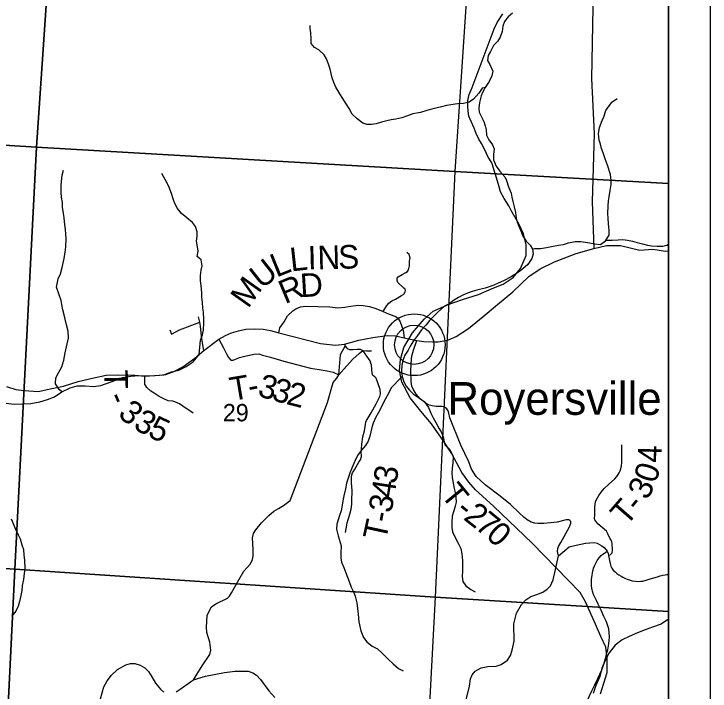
# Model space of a CAD drawing. Extents: x 0 to 44, y -23.8 to 22.
# Drawn here: x 7.321 to 9, y 15.074 to 16.706 of the extents above; entities that cross this region are included whole.
import ezdxf

# ---------------------------------------------------------------- set-up
doc = ezdxf.new("R2010")
doc.units = 0
for name, color, linetype in [('Default', 7, 'Continuous'), ('GM_X_County_Road', 7, 'Continuous'), ('GM_X_Minor_River', 7, 'Continuous'), ('GM_X_Rail_Line', 7, 'Continuous'), ('GM_X_Section', 7, 'Continuous'), ('GM_X_Section_Text', 7, 'Continuous'), ('GM_X_Township_Road', 7, 'Continuous'), ('GM_X_Township_Road_Text', 7, 'Continuous'), ('GM_X_Unincorporated', 7, 'Continuous'), ('GM_X_Unincorporated_Location', 7, 'Continuous'), ('GM_X_Unincorporated_Text', 7, 'Continuous'), ('SH_Cut_Line', 7, 'Continuous'), ('SH_Data', 7, 'Continuous')]:
    doc.layers.add(name, color=color, linetype=linetype)

msp = doc.modelspace()

# ---------------------------------------------------------------- linework, layer by layer
at = {"layer": 'Default'}
msp.add_lwpolyline([(7.2787, 14.3616), (7.5613, 14.343), (8.045, 14.3111), (8.4778, 14.2825), (8.9, 14.2547), (8.9, 20.3521), (8.6785, 20.3684), (7.6577, 20.4476), (7.4495, 20.4611), (7.016, 20.4891)], dxfattribs=at)
for points in [[(8.9, 16.2979), (8.9, 17.3085), (8.4522, 17.3376), (8.3848, 16.3266)], [(8.9, 15.2663), (8.9, 16.2979), (8.3848, 16.3266), (8.3369, 15.3004)], [(8.9, 14.2455), (8.9, 15.2663), (8.3369, 15.3004), (8.2829, 14.2852)]]:
    msp.add_lwpolyline(points, close=True, dxfattribs=at)
at = {"layer": 'GM_X_County_Road'}
for points in [[(7.3035, 15.808), (7.3263, 15.8012), (7.3453, 15.7989), (7.381, 15.7962), (7.4091, 15.8025), (7.4406, 15.8091), (7.4761, 15.8202), (7.5144, 15.8296), (7.5439, 15.8357), (7.5709, 15.8361), (7.6133, 15.8353), (7.6373, 15.8336), (7.6712, 15.8354), (7.688, 15.8377), (7.7072, 15.8445), (7.729, 15.8555), (7.7579, 15.8767), (7.7796, 15.8948), (7.8153, 15.9221), (7.8316, 15.9312), (7.846, 15.9381), (7.8626, 15.9427), (7.8809, 15.9463), (7.9005, 15.9476), (7.9224, 15.9469), (7.9397, 15.9437), (7.9599, 15.9378), (8.0603, 15.912), (8.0967, 15.9084), (8.1181, 15.9106), (8.1534, 15.9198), (8.1865, 15.9263), (8.2216, 15.9316), (8.2416, 15.9304), (8.262, 15.9259), (8.2929, 15.9194), (8.3094, 15.9171), (8.3305, 15.916), (8.344, 15.916), (8.3578, 15.9187), (8.3695, 15.9206), (8.3874, 15.9287), (8.4174, 15.9483), (8.4525, 15.9769), (8.4872, 16.006), (8.5245, 16.0365), (8.5627, 16.0731), (8.5901, 16.0919), (8.6251, 16.1092), (8.6772, 16.129), (8.7196, 16.1411), (8.7505, 16.1479), (8.7839, 16.1481), (8.8305, 16.1371), (8.862, 16.1394), (8.8922, 16.1349), (8.9, 16.1351)], [(8.1181, 15.9106), (8.1198, 15.9053), (8.1249, 15.8996), (8.1302, 15.8977), (8.1382, 15.8977), (8.1492, 15.8982), (8.1559, 15.8983), (8.1626, 15.8948), (8.1717, 15.8946), (8.1782, 15.8941), (8.1837, 15.8941)]]:
    msp.add_lwpolyline(points, dxfattribs=at)
at = {"layer": 'GM_X_Minor_River'}
for points in [[(8.5238, 16.7085), (8.5129, 16.6997), (8.5045, 16.688), (8.5004, 16.677), (8.4985, 16.6641), (8.494, 16.65), (8.4871, 16.6398), (8.4781, 16.6303), (8.4705, 16.6159), (8.4652, 16.606), (8.4633, 16.5943), (8.469, 16.5844), (8.4765, 16.5685), (8.4739, 16.5571), (8.4671, 16.5435), (8.4576, 16.5294), (8.452, 16.5188), (8.4478, 16.5089), (8.4444, 16.493), (8.4425, 16.4794), (8.4436, 16.4695), (8.4478, 16.46), (8.4542, 16.4467), (8.4576, 16.4365), (8.4599, 16.4267), (8.4606, 16.4141), (8.4663, 16.4031), (8.4754, 16.3906), (8.4795, 16.3808), (8.4776, 16.3679), (8.4776, 16.3546), (8.4841, 16.3391), (8.4931, 16.3273), (8.5048, 16.314), (8.5094, 16.3046), (8.5143, 16.2898), (8.5203, 16.2742), (8.5222, 16.2644), (8.5245, 16.2545), (8.5275, 16.2416), (8.5305, 16.2276), (8.5328, 16.2139), (8.5351, 16.2045), (8.5388, 16.195), (8.5437, 16.1836), (8.5487, 16.1711), (8.5566, 16.159), (8.566, 16.1491), (8.5721, 16.1392), (8.5732, 16.1282), (8.5706, 16.1169), (8.5604, 16.1025), (8.5486, 16.0918), (8.5377, 16.0839), (8.5203, 16.0725), (8.5018, 16.063), (8.4893, 16.0573), (8.4783, 16.0527), (8.4677, 16.0489), (8.4575, 16.0455), (8.4379, 16.0402), (8.4262, 16.0371), (8.4148, 16.0333), (8.4042, 16.0288), (8.3936, 16.0231), (8.3815, 16.0155), (8.3706, 16.0079), (8.3596, 16.0018), (8.3445, 15.9885), (8.3343, 15.9787), (8.3237, 15.9677), (8.3158, 15.9571), (8.3044, 15.9449), (8.2942, 15.9312), (8.2848, 15.9187), (8.2772, 15.9058), (8.2723, 15.8963), (8.2643, 15.8838), (8.259, 15.8713), (8.2568, 15.8588), (8.256, 15.8451)], [(8.0691, 16.6076), (8.0562, 16.62), (8.046, 16.6257), (8.0381, 16.6352), (8.0385, 16.6466), (8.0374, 16.661), (8.0355, 16.6716), (8.0359, 16.6781)], [(8.4576, 16.5294), (8.4508, 16.5275), (8.4425, 16.515), (8.4297, 16.501), (8.4191, 16.4938), (8.4051, 16.4903), (8.3911, 16.4896), (8.3752, 16.4869), (8.3643, 16.4854), (8.3525, 16.4823), (8.3423, 16.4797), (8.3287, 16.4766), (8.317, 16.4732), (8.3019, 16.4687), (8.2834, 16.4652), (8.2701, 16.461), (8.2565, 16.4561), (8.2422, 16.4523), (8.2308, 16.4508), (8.2202, 16.4485), (8.2078, 16.4458), (8.1949, 16.4417), (8.1836, 16.4401), (8.1726, 16.4397), (8.1624, 16.4431), (8.1488, 16.4538), (8.1371, 16.4644), (8.1295, 16.478), (8.1212, 16.4924), (8.1144, 16.5023), (8.1072, 16.514), (8.0978, 16.53), (8.0925, 16.5413), (8.0887, 16.5527), (8.0842, 16.5728), (8.0796, 16.5853), (8.0747, 16.5982), (8.0691, 16.6076)], [(8.5721, 16.1392), (8.5774, 16.1408), (8.5914, 16.1408), (8.6054, 16.1431), (8.6175, 16.1457), (8.6341, 16.1491), (8.6466, 16.1507), (8.6587, 16.1548), (8.6745, 16.1579), (8.6881, 16.1579), (8.7055, 16.1553), (8.7218, 16.1526), (8.7358, 16.1503), (8.7482, 16.1594), (8.7566, 16.1735), (8.7569, 16.1845), (8.7554, 16.2008), (8.7543, 16.2141), (8.7535, 16.2254), (8.7539, 16.244), (8.7551, 16.2562), (8.7566, 16.2656), (8.7592, 16.2808), (8.7611, 16.2952), (8.7615, 16.3047), (8.76, 16.3195), (8.7528, 16.3415), (8.7479, 16.3544), (8.7422, 16.3714), (8.7385, 16.3817), (8.7354, 16.3923), (8.7328, 16.4018), (8.7309, 16.4173), (8.7336, 16.4325), (8.7396, 16.4492), (8.7438, 16.4587), (8.7483, 16.4735), (8.7634, 16.494), (8.7759, 16.5023)], [(7.4371, 15.7958), (7.4308, 15.8013), (7.4213, 15.8146), (7.4228, 15.829), (7.4289, 15.8412), (7.4372, 15.8556), (7.4421, 15.8719), (7.4452, 15.8893), (7.4497, 15.9113), (7.4527, 15.925), (7.452, 15.9421), (7.4482, 15.9568), (7.4448, 15.9709), (7.4429, 15.9815), (7.4395, 15.9932), (7.4369, 16.0061), (7.435, 16.0156), (7.4244, 16.0475), (7.4282, 16.0676), (7.4335, 16.0801), (7.4376, 16.0949), (7.4429, 16.1165), (7.4448, 16.132), (7.4463, 16.1453), (7.4475, 16.165), (7.4467, 16.1753), (7.446, 16.1867), (7.4433, 16.2052), (7.4422, 16.2159), (7.4407, 16.2257), (7.4388, 16.2409), (7.4381, 16.2515), (7.4358, 16.2644), (7.435, 16.2765), (7.4354, 16.2947), (7.4373, 16.3175), (7.4407, 16.33)], [(7.7682, 15.8854), (7.7714, 15.9199), (7.7763, 15.9332), (7.7782, 15.9449), (7.779, 15.9609), (7.779, 15.9703), (7.7782, 15.9878), (7.7771, 15.9973), (7.776, 16.0105), (7.7748, 16.0246), (7.7741, 16.0344), (7.7726, 16.0515), (7.7714, 16.0632), (7.7711, 16.0761), (7.7729, 16.0887), (7.7752, 16.0993), (7.773, 16.1133), (7.7631, 16.1216), (7.7654, 16.1349), (7.7643, 16.1452), (7.7616, 16.1588), (7.7631, 16.171), (7.7635, 16.1808), (7.7594, 16.1941), (7.7522, 16.2039), (7.7382, 16.2145), (7.7253, 16.2255), (7.7159, 16.2373), (7.7091, 16.2494), (7.7057, 16.2608), (7.7012, 16.2733), (7.6947, 16.2904), (7.6864, 16.3074), (7.6781, 16.3218)], [(8.7482, 16.1594), (8.7486, 16.161), (8.7641, 16.1614), (8.7781, 16.1621), (8.7898, 16.1625), (8.8012, 16.1614), (8.8133, 16.1583), (8.8238, 16.1553), (8.8367, 16.1519), (8.8488, 16.1489), (8.859, 16.1474), (8.8726, 16.1462), (8.8862, 16.1466), (8.896, 16.1493), (8.9, 16.1516)], [(7.3026, 15.7681), (7.3219, 15.7655), (7.342, 15.767), (7.3624, 15.7677), (7.384, 15.7711), (7.4022, 15.7768), (7.4193, 15.7833), (7.4371, 15.7958), (7.4568, 15.8053), (7.4742, 15.8098), (7.4931, 15.8098), (7.5136, 15.8087), (7.531, 15.8105), (7.5556, 15.8193), (7.5837, 15.8303), (7.6034, 15.8329), (7.6223, 15.8348), (7.6424, 15.834), (7.6617, 15.8352), (7.6829, 15.8367), (7.7014, 15.8439), (7.7189, 15.848), (7.7367, 15.8568), (7.7537, 15.8682), (7.7682, 15.8853), (7.7682, 15.8854)], [(8.2579, 15.8326), (8.2314, 15.8053), (8.2242, 15.7916), (8.2144, 15.7727), (8.2061, 15.756), (8.2004, 15.7457), (8.1936, 15.7332), (8.1876, 15.7203), (8.1842, 15.7097), (8.1819, 15.6991), (8.1792, 15.6888), (8.1758, 15.6763), (8.1694, 15.6664), (8.1592, 15.6551), (8.1513, 15.6444), (8.1448, 15.6323), (8.1407, 15.6224), (8.1365, 15.6118), (8.1323, 15.602), (8.1236, 15.5758), (8.1206, 15.5614), (8.1172, 15.5447), (8.1142, 15.5329), (8.113, 15.5223), (8.1104, 15.5086), (8.1066, 15.4976), (8.1032, 15.487), (8.1002, 15.4768), (8.099, 15.4646), (8.1036, 15.4483), (8.1104, 15.4241), (8.1096, 15.4081), (8.1096, 15.3956), (8.1111, 15.385), (8.1168, 15.3721), (8.1213, 15.3592), (8.1259, 15.3486), (8.1296, 15.3384), (8.1345, 15.3247), (8.1402, 15.3137), (8.1444, 15.3031), (8.1482, 15.2868), (8.15, 15.2735), (8.1512, 15.2599), (8.1531, 15.2413), (8.1576, 15.2197), (8.1644, 15.2034), (8.1727, 15.1928), (8.1855, 15.1829), (8.198, 15.1761), (8.2094, 15.1659), (8.2237, 15.1511), (8.2362, 15.1397), (8.249, 15.1291), (8.2596, 15.1234)], [(8.256, 15.8451), (8.2579, 15.8326), (8.2609, 15.8224), (8.2666, 15.8099), (8.2753, 15.7993), (8.2847, 15.7898), (8.2991, 15.7799), (8.3104, 15.7724), (8.321, 15.7576), (8.3263, 15.7443), (8.3323, 15.7325), (8.3391, 15.7216), (8.3463, 15.7083), (8.3512, 15.6988), (8.3561, 15.6867), (8.3607, 15.6677), (8.3728, 15.6563), (8.3803, 15.6397), (8.3799, 15.6245), (8.3781, 15.6108), (8.3769, 15.6006), (8.378, 15.5888), (8.3807, 15.5756), (8.3833, 15.5627), (8.3856, 15.5528), (8.3871, 15.5418), (8.3875, 15.5297), (8.3856, 15.5198), (8.3822, 15.5084), (8.378, 15.4955), (8.3769, 15.4807), (8.3773, 15.4682), (8.3792, 15.458), (8.3856, 15.4447), (8.3928, 15.4311), (8.3988, 15.4182), (8.4018, 15.4049), (8.403, 15.389), (8.4033, 15.375), (8.4029, 15.3636), (8.4026, 15.3507), (8.4037, 15.3385), (8.4113, 15.3279), (8.4234, 15.3192), (8.4332, 15.3135)], [(7.3147, 15.4891), (7.3249, 15.4649), (7.3313, 15.4509), (7.3366, 15.4414), (7.3404, 15.4266), (7.3441, 15.4152), (7.3453, 15.4016), (7.3468, 15.3902), (7.3475, 15.3701), (7.346, 15.3576), (7.3445, 15.3432), (7.3415, 15.3287), (7.3407, 15.3166), (7.3384, 15.3045), (7.335, 15.2901), (7.3316, 15.2791), (7.3263, 15.2669), (7.3165, 15.2551)], [(8.9, 15.2474), (8.8819, 15.2356), (8.8611, 15.2281), (8.8436, 15.2216), (8.8251, 15.2144), (8.805, 15.206), (8.7879, 15.1977), (8.7709, 15.1852), (8.7564, 15.1665), (8.7473, 15.1483), (8.7389, 15.1297), (8.734, 15.1095), (8.7244, 15.0875), (8.7183, 15.0685)]]:
    msp.add_lwpolyline(points, dxfattribs=at)
at = {"layer": 'GM_X_Rail_Line'}
msp.add_lwpolyline([(8.7356, 15.0673), (8.7519, 15.1189), (8.7519, 15.1529), (8.7489, 15.1802), (8.7369, 15.206), (8.7236, 15.2355), (8.6994, 15.2894), (8.6866, 15.3119), (8.5707, 15.431), (8.4774, 15.5203), (8.4343, 15.5591), (8.4183, 15.5776), (8.4013, 15.6013), (8.3761, 15.6475), (8.3561, 15.6784), (8.3415, 15.6998), (8.3286, 15.7183), (8.3029, 15.7489), (8.2772, 15.7811), (8.2568, 15.8187), (8.2514, 15.847), (8.2538, 15.8736), (8.2619, 15.9026), (8.2828, 15.9379), (8.3104, 15.9707), (8.3326, 15.9896), (8.3705, 16.0072), (8.4034, 16.018), (8.4414, 16.0299), (8.4746, 16.0446), (8.5012, 16.0554), (8.5249, 16.0711), (8.543, 16.093), (8.5563, 16.1239), (8.5563, 16.1496), (8.5498, 16.1762), (8.5386, 16.2003), (8.5205, 16.2327), (8.5144, 16.2441), (8.5031, 16.2611), (8.4946, 16.2772), (8.4913, 16.2894), (8.4825, 16.3192), (8.474, 16.3472), (8.4646, 16.3612), (8.455, 16.382), (8.4489, 16.3939), (8.4426, 16.4042), (8.4361, 16.4184), (8.431, 16.4308), (8.4179, 16.4602), (8.4167, 16.4723), (8.4155, 16.4844), (8.4159, 16.4974), (8.4191, 16.5118), (8.426, 16.5294), (8.479, 16.6703), (8.487, 16.6856), (8.5002, 16.7065)], dxfattribs=at)
at = {"layer": 'GM_X_Section'}
for points in [[(6.4419, 17.4633), (7.4446, 17.3999), (7.376, 16.3855), (6.3745, 16.447)], [(7.4446, 17.3999), (8.4522, 17.3376), (8.3848, 16.3266), (7.376, 16.3855)], [(6.3745, 16.447), (7.376, 16.3855), (7.3239, 15.368), (6.3163, 15.4337)], [(7.376, 16.3855), (8.3848, 16.3266), (8.3369, 15.3004), (7.3239, 15.368)], [(7.3239, 15.368), (7.2726, 14.3512), (6.2643, 14.4116), (6.3163, 15.4337)], [(8.3369, 15.3004), (8.2829, 14.2852), (7.2726, 14.3512), (7.3239, 15.368)]]:
    msp.add_lwpolyline(points, close=True, dxfattribs=at)
at = {"layer": 'GM_X_Township_Road'}
for points in [[(8.6754, 16.9848), (8.6742, 16.9786), (8.6726, 16.9703), (8.6765, 16.9471), (8.6955, 16.895), (8.7171, 16.722), (8.714, 16.5506), (8.7202, 16.4177), (8.7155, 16.254), (8.7196, 16.1411)], [(8.2114, 15.9892), (8.2204, 16.0036), (8.225, 16.0092), (8.233, 16.0149), (8.2417, 16.0187), (8.256, 16.0274), (8.2619, 16.0311), (8.2651, 16.0367), (8.2656, 16.0395), (8.2647, 16.0426), (8.2619, 16.0454), (8.2472, 16.0589), (8.2451, 16.0642), (8.2458, 16.0698), (8.2481, 16.0724), (8.2577, 16.0784), (8.2663, 16.0828), (8.2703, 16.0859), (8.273, 16.0896), (8.2754, 16.0991), (8.2754, 16.111), (8.2765, 16.1173), (8.2742, 16.1262), (8.2686, 16.1315)], [(7.9599, 15.9378), (7.9629, 15.9499), (7.9727, 15.9646), (7.9812, 15.9789), (7.9936, 15.991), (8.0008, 15.9959), (8.0122, 16.0002), (8.0256, 16.0018), (8.0835, 16.0007), (8.1024, 15.9982), (8.1195, 15.9995), (8.1281, 16.0015), (8.1518, 16.0048), (8.1632, 16.0039), (8.1791, 16.0015), (8.1942, 15.9962), (8.2114, 15.9892), (8.2261, 15.9827), (8.242, 15.9774), (8.2482, 15.9726), (8.253, 15.9643), (8.2596, 15.9443), (8.262, 15.9259)], [(7.7796, 15.8948), (7.7755, 15.9183), (7.7725, 15.9373), (7.7715, 15.9538), (7.7696, 15.9634), (7.7667, 15.9759)], [(7.6973, 15.9452), (7.7014, 15.9343), (7.721, 15.9448), (7.7696, 15.9634)], [(7.8153, 15.9221), (7.827, 15.9018), (7.8339, 15.8875), (7.8388, 15.8783), (7.8447, 15.8721), (7.8499, 15.8721), (7.8652, 15.878), (7.8812, 15.8822), (7.8894, 15.8836), (7.9002, 15.8865), (7.9116, 15.8875), (7.9208, 15.8842), (7.9403, 15.8787), (7.9724, 15.8692), (8.0181, 15.8571), (8.0364, 15.8527), (8.0575, 15.8495), (8.0769, 15.8465), (8.0911, 15.8428), (8.1052, 15.8367), (8.1232, 15.8573), (8.1384, 15.8739), (8.154, 15.8876), (8.1626, 15.8948)], [(8.2791, 15.8202), (8.2785, 15.8462), (8.2804, 15.8757), (8.2819, 15.8846), (8.2852, 15.8957), (8.2929, 15.9194)], [(7.7542, 15.1014), (7.7752, 15.1352), (7.7934, 15.1623), (7.7963, 15.1727), (7.7941, 15.1919), (7.7866, 15.2157), (7.7858, 15.2287), (7.7876, 15.2561), (7.792, 15.2669), (7.7977, 15.277), (7.8086, 15.2849), (7.8363, 15.2985), (7.8415, 15.3032), (7.8462, 15.311), (7.8637, 15.3423), (7.8756, 15.3632), (7.8915, 15.3812), (7.8969, 15.3917), (7.898, 15.3996), (7.898, 15.4155), (7.8969, 15.4435), (7.8994, 15.4543), (7.9046, 15.4632), (7.918, 15.4794), (7.9362, 15.4971), (7.9482, 15.5079), (7.959, 15.5142), (7.9716, 15.5216), (7.9871, 15.5336), (8.0771, 15.7701), (8.0915, 15.818), (8.0999, 15.8284), (8.1052, 15.8367), (8.1091, 15.8846), (8.1106, 15.889), (8.1198, 15.9053)], [(8.1212, 15.4562), (8.1223, 15.4657), (8.1241, 15.4738), (8.1252, 15.4796), (8.1315, 15.5004), (8.1342, 15.5129), (8.1363, 15.5248), (8.1365, 15.5335), (8.1372, 15.5572), (8.1356, 15.5767), (8.1352, 15.5902), (8.1361, 15.5956), (8.138, 15.6004), (8.1422, 15.6078), (8.1541, 15.6273), (8.1569, 15.6319), (8.1595, 15.6397), (8.1595, 15.6436), (8.1589, 15.6486), (8.1597, 15.6583), (8.1603, 15.6692), (8.163, 15.6867), (8.1671, 15.7015), (8.1681, 15.7119), (8.1699, 15.7222), (8.1713, 15.7262), (8.173, 15.7286), (8.1829, 15.7451), (8.1952, 15.7669), (8.204, 15.784), (8.2052, 15.7905), (8.2047, 15.801), (8.1995, 15.8152), (8.1947, 15.8283), (8.1918, 15.8315), (8.1865, 15.835), (8.1848, 15.8404), (8.1846, 15.8496), (8.1833, 15.8609), (8.1823, 15.8645), (8.18, 15.8704), (8.1767, 15.876), (8.1626, 15.8948)], [(7.7538, 15.7443), (7.7283, 15.7613), (7.7204, 15.7663), (7.7095, 15.7712), (7.7043, 15.7728), (7.6932, 15.7738), (7.683, 15.7785), (7.6719, 15.784), (7.6592, 15.792), (7.6511, 15.7975), (7.6415, 15.8059), (7.6374, 15.8144), (7.6373, 15.8336)], [(8.6348, 15.4004), (8.6318, 15.4109), (8.6328, 15.4181), (8.6349, 15.4227), (8.6405, 15.4324), (8.6609, 15.4704), (8.6646, 15.4792), (8.6645, 15.4829), (8.6622, 15.4855), (8.6591, 15.4868), (8.6529, 15.4869), (8.6309, 15.4816), (8.5994, 15.4784), (8.5845, 15.4781), (8.5778, 15.4793), (8.5686, 15.4816), (8.559, 15.4872), (8.551, 15.4935), (8.5405, 15.5034), (8.519, 15.5239), (8.4936, 15.5443), (8.458, 15.5716), (8.4363, 15.5918), (8.4251, 15.6091), (8.4182, 15.6266), (8.3986, 15.6667), (8.3722, 15.733), (8.37, 15.7438), (8.3683, 15.75), (8.3654, 15.7544), (8.3617, 15.757), (8.358, 15.7591), (8.3532, 15.7599), (8.3396, 15.7602), (8.3298, 15.7616), (8.3201, 15.7641), (8.3127, 15.769), (8.3011, 15.7787), (8.2914, 15.79), (8.2841, 15.8016), (8.2809, 15.8088), (8.2791, 15.8202)], [(8.7552, 15.4014), (8.7592, 15.403), (8.7624, 15.4055), (8.7636, 15.4076), (8.7644, 15.414), (8.7644, 15.4192), (8.7636, 15.4245), (8.7638, 15.4299), (8.7631, 15.435), (8.7615, 15.4383), (8.7579, 15.4425), (8.7534, 15.4534), (8.75, 15.4601), (8.7295, 15.4772), (8.722, 15.4868), (8.7216, 15.49), (8.7221, 15.4979), (8.7224, 15.507), (8.7225, 15.5173), (8.7232, 15.5247), (8.7237, 15.5302), (8.7254, 15.5348), (8.7316, 15.5455), (8.7377, 15.5537), (8.7448, 15.5625), (8.7554, 15.5725), (8.77, 15.5857), (8.7753, 15.5916), (8.7785, 15.5961), (8.7808, 15.6003), (8.7828, 15.6051), (8.7845, 15.6103), (8.7864, 15.6173), (8.787, 15.625), (8.7871, 15.633), (8.787, 15.6393), (8.7869, 15.6531), (8.7872, 15.668)], [(8.408, 15.0373), (8.4195, 15.0861), (8.4224, 15.1037), (8.4266, 15.1131), (8.4339, 15.1225), (8.4404, 15.1267), (8.448, 15.1301), (8.4645, 15.1332), (8.4845, 15.134), (8.496, 15.138), (8.5113, 15.1485), (8.519, 15.16), (8.523, 15.1729), (8.5278, 15.195), (8.5266, 15.236), (8.5333, 15.2624), (8.5454, 15.2833), (8.5558, 15.2946), (8.5675, 15.3021), (8.5823, 15.3067), (8.5968, 15.3127), (8.6071, 15.3198), (8.6152, 15.3276), (8.6213, 15.3425), (8.6275, 15.3671), (8.6348, 15.4004), (8.6601, 15.4216), (8.6775, 15.4261), (8.6994, 15.4305), (8.7203, 15.4328), (8.7274, 15.4311), (8.7391, 15.4242), (8.7444, 15.42), (8.7521, 15.4113), (8.7544, 15.4062), (8.7552, 15.4014), (8.7573, 15.3892), (8.759, 15.3821), (8.7608, 15.3751), (8.7632, 15.3704), (8.7665, 15.3657), (8.7708, 15.3615), (8.7753, 15.3579), (8.7801, 15.3547), (8.7855, 15.3514), (8.7896, 15.3492), (8.7959, 15.3458), (8.7999, 15.3437), (8.8124, 15.3403), (8.8198, 15.3392), (8.8276, 15.3387), (8.833, 15.339), (8.8377, 15.3396), (8.846, 15.3419), (8.8557, 15.3449), (8.8731, 15.3499), (8.8795, 15.3518), (8.8864, 15.3538), (8.8914, 15.3546), (8.8961, 15.3549), (8.9, 15.3549)], [(8.7033, 15.0505), (8.7149, 15.0747), (8.7222, 15.0895), (8.7297, 15.1049), (8.739, 15.1256), (8.744, 15.1393), (8.7493, 15.1581), (8.7514, 15.1664), (8.7531, 15.1737), (8.7552, 15.183), (8.7564, 15.1954), (8.7573, 15.2048), (8.7566, 15.2153), (8.7555, 15.2245), (8.7536, 15.2317), (8.7511, 15.2384), (8.7493, 15.243), (8.744, 15.2543), (8.7371, 15.2696), (8.7302, 15.2834), (8.7259, 15.2928), (8.7192, 15.3073), (8.7164, 15.3155), (8.7148, 15.3224), (8.7141, 15.3282), (8.7137, 15.334), (8.7137, 15.338), (8.7141, 15.344), (8.7156, 15.3529), (8.7164, 15.359), (8.7174, 15.3635), (8.7192, 15.3708), (8.7213, 15.3765), (8.7237, 15.3812), (8.7256, 15.3845), (8.7279, 15.3888), (8.7305, 15.3925), (8.7325, 15.3953), (8.7376, 15.4008), (8.7415, 15.4042), (8.7451, 15.4066), (8.7521, 15.4113)], [(7.5305, 15.0557), (7.5381, 15.0842), (7.546, 15.0987), (7.5564, 15.1125), (7.5712, 15.1265), (7.591, 15.1374), (7.6027, 15.1405), (7.6127, 15.1405), (7.6259, 15.1369), (7.6371, 15.1303), (7.646, 15.1214), (7.6541, 15.1084), (7.663, 15.0937), (7.675, 15.0792), (7.6829, 15.0713)], [(7.7124, 15.0725), (7.7222, 15.0791), (7.7472, 15.0968), (7.7542, 15.1014), (7.7834, 15.1104), (7.8288, 15.1194), (7.8547, 15.1226), (7.8753, 15.1226), (7.886, 15.1224), (7.8976, 15.118), (7.9063, 15.1126), (7.9159, 15.1026), (7.936, 15.0749), (7.9501, 15.0591)]]:
    msp.add_lwpolyline(points, dxfattribs=at)
at = {"layer": 'GM_X_Unincorporated'}
for radius in [0.0744, 0.0472]:
    msp.add_circle((8.2866, 15.9089), radius, dxfattribs=at)
at = {"layer": 'GM_X_Unincorporated_Location'}
msp.add_line((8.2866, 15.9089), (8.2866, 15.9089), dxfattribs=at)
at = {"layer": 'SH_Cut_Line'}
msp.add_lwpolyline([(2.838, 14.1), (8.9, 14.1), (8.9, 20.9), (6.8158, 20.9)], dxfattribs=at)
at = {"layer": 'SH_Data'}
for p, q in [((9, 21), (9, 14)), ((8.9, 20.9), (8.9, 14.1))]:
    msp.add_line(p, q, dxfattribs=at)

# ---------------------------------------------------------------- texts
at = {"layer": 'GM_X_Section_Text'}
msp.add_text('29', height=0.04186, rotation=0, dxfattribs=at).set_placement((7.8252, 15.7244))
at = {"layer": 'GM_X_Township_Road_Text'}
for s, rotation, p in [('N', 1.3698, (8.0539, 16.0908)), ('S', 1.3686, (8.1039, 16.092)), ('L', 6.3404, (7.9897, 16.0856)), ('I', 1.4637, (8.0306, 16.0902)), ('U', 38.2069, (7.9186, 16.0418)), ('L', 22.1161, (7.9543, 16.0706)), ('D', 3.368, (8.013, 16.0234)), ('M', 54.6771, (7.8859, 15.9946)), ('R', 22.7222, (7.9749, 16.0065)), ('T', 271.3244, (7.539, 15.8481)), ('T', 9.6497, (7.8468, 15.7734)), ('3', 344.1207, (7.9066, 15.7859)), ('3', 344.2848, (7.9404, 15.7763)), ('2', 345.8424, (7.9757, 15.7664)), ('-', 11.6683, (7.8909, 15.7809)), ('-', 292.6521, (7.5448, 15.7832)), ('3', 318.2782, (7.5697, 15.7393)), ('3', 330.6938, (7.6068, 15.7082)), ('5', 334.9761, (7.6414, 15.689)), ('4', 88.8056, (8.8825, 15.6241)), ('3', 81.0166, (8.2435, 15.5718)), ('0', 72.0645, (8.8687, 15.573)), ('4', 80.8357, (8.2379, 15.537)), ('T', 309.2829, (8.3484, 15.5467)), ('3', 62.8739, (8.849, 15.5327)), ('3', 80.115, (8.2317, 15.5018)), ('T', 48.938, (8.7977, 15.4702)), ('-', 50.337, (8.8266, 15.5034)), ('-', 320.4799, (8.3839, 15.5052)), ('2', 321.8, (8.403, 15.4895)), ('-', 79.3361, (8.2273, 15.478)), ('7', 320.9607, (8.4303, 15.468)), ('T', 77.7924, (8.218, 15.4348)), ('0', 317.1494, (8.4568, 15.4466))]:
    msp.add_text(s, height=0.0568, rotation=rotation, dxfattribs=at).set_placement(p)
at = {"layer": 'GM_X_Unincorporated_Text'}
msp.add_text('Royersville', height=0.078977, rotation=0, dxfattribs=at).set_placement((8.3668, 15.7401))

doc.saveas('drawing.dxf')
